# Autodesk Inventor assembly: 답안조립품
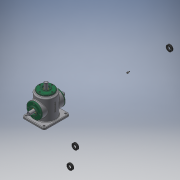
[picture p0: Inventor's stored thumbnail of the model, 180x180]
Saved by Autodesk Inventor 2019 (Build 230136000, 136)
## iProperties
Created: 2020-12
Part Number: 답안조립품
Material: 일반
Document SubType Name: Assembly
Designer: jun-1-19
Author: jun-1-19
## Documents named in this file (16)
- C:\Users\jun-1-19\Desktop\701207V1004\답안조립품.iam
- C:\Users\jun-1-19\Desktop\701207V1004\본체.ipt
- C:\Users\jun-1-19\Desktop\701207V1004\메인 베벨기어.ipt
- C:\Users\jun-1-19\Desktop\701207V1004\메인 축.ipt
- 메인 축.ipt
- C:\Users\jun-1-19\Desktop\701207V1004\베어링 6203.ipt
- C:\Users\jun-1-19\Desktop\701207V1004\볼트 M4.ipt
- 볼트 M4.ipt
- C:\Users\jun-1-19\Desktop\701207V1004\서브 베벨기어.ipt
- C:\Users\jun-1-19\Desktop\701207V1004\서브 축.ipt
- 서브 축.ipt
- C:\Users\jun-1-19\Desktop\701207V1004\오일 실.ipt
- 오일 실.ipt
- C:\Users\jun-1-19\Desktop\701207V1004\커버.ipt
- C:\Users\jun-1-19\Desktop\701207V1004\키 4x4.ipt
- C:\Users\jun-1-19\Desktop\701207V1004\키 5x5.ipt
